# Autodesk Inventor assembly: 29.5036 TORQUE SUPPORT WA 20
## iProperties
Created: 2007-07
Part Number: 29.5036 TORQUE SUPPORT WA 20
Document SubType Name: Assembly
Designer: Andy Moles
Author: Andy Moles
